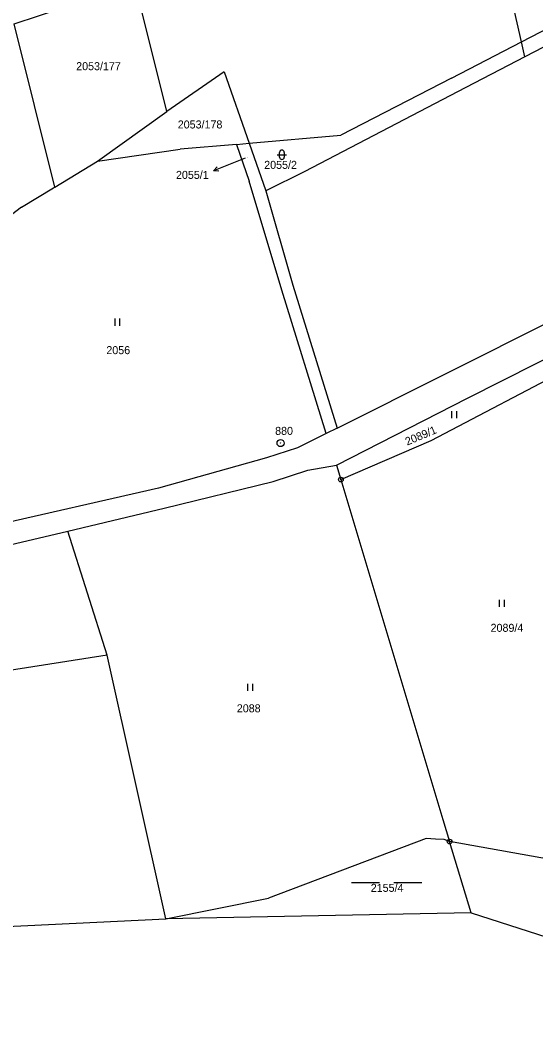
# Model space of a CAD drawing. Extents: x -736345 to -729997, y -1130177 to -1122501.
# Drawn here: x -732550.6 to -732441, y -1128475.7 to -1128261.6 of the extents above; entities that cross this region are included whole.
import ezdxf

# ---------------------------------------------------------------- set-up
doc = ezdxf.new("R2010")
doc.units = 0
for name, color, linetype in [('Vrstva 1', 7, 'Continuous'), ('Vrstva 16', 7, 'Continuous'), ('Vrstva 17', 7, 'Continuous'), ('Vrstva 18', 7, 'Continuous'), ('Vrstva 25', 7, 'Continuous')]:
    doc.layers.add(name, color=color, linetype=linetype)

msp = doc.modelspace()

# ---------------------------------------------------------------- linework, layer by layer
at = {"layer": 'Vrstva 1'}
for points in [[(-732444.11, -1128266.16), (-732456.89, -1128209.92)], [(-732444.11, -1128266.16), (-732412.86, -1128249.98)], [(-732519.44, -1128280.95), (-732526.56, -1128252.5)], [(-732412.09, -1128253.1), (-732443.39, -1128269.35)], [(-732551.87, -1128262.39), (-732541.52, -1128258.95)], [(-732543.26, -1128297.02), (-732551.87, -1128262.39)], [(-732459, -1128273.87), (-732444.11, -1128266.16)], [(-732443.39, -1128269.35), (-732444.11, -1128266.16)], [(-732443.39, -1128269.35), (-732457.71, -1128276.78)], [(-732507.28, -1128272.56), (-732519.44, -1128280.95)], [(-732507.28, -1128272.56), (-732501.97, -1128287.72)], [(-732459, -1128273.87), (-732482.51, -1128285.99)], [(-732457.71, -1128276.78), (-732490.15, -1128293.7)], [(-732483.26, -1128348.19), (-732344.42, -1128278.67)], [(-732534.19, -1128291.5), (-732519.44, -1128280.95)], [(-732501.97, -1128287.72), (-732482.51, -1128285.99)], [(-732534.19, -1128291.5), (-732516.62, -1128288.99)], [(-732504.68, -1128287.96), (-732516.62, -1128288.99)], [(-732504.68, -1128287.96), (-732501.97, -1128287.72)], [(-732504.68, -1128287.96), (-732501.96, -1128295.78)], [(-732501.97, -1128287.72), (-732498.43, -1128297.81)], [(-732543.26, -1128297.02), (-732534.19, -1128291.5)], [(-732490.15, -1128293.7), (-732498.43, -1128297.81)], [(-732494.99, -1128318.93), (-732501.96, -1128295.78)], [(-732550.32, -1128301.31), (-732543.55, -1128297.2)], [(-732543.55, -1128297.2), (-732543.26, -1128297.02)], [(-732498.43, -1128297.81), (-732492.65, -1128317.86)], [(-732550.32, -1128301.31), (-732558.05, -1128307.2)], [(-732485.62, -1128349.38), (-732494.99, -1128318.93)], [(-732492.65, -1128317.86), (-732483.26, -1128348.19)], [(-732455.55, -1128341.87), (-732433.54, -1128330.73)], [(-732463.28, -1128350.81), (-732432.78, -1128334.86)], [(-732483.4, -1128356.05), (-732455.55, -1128341.87)], [(-732485.62, -1128349.38), (-732491.7, -1128352.42)], [(-732483.26, -1128348.19), (-732485.62, -1128349.38)], [(-732482.47, -1128359.13), (-732463.28, -1128350.81)], [(-732491.7, -1128352.42), (-732498.29, -1128354.48)], [(-732498.29, -1128354.48), (-732521.24, -1128360.95)], [(-732489.52, -1128357.12), (-732483.4, -1128356.05)], [(-732483.4, -1128356.05), (-732482.47, -1128359.13)], [(-732496.89, -1128359.52), (-732489.52, -1128357.12)], [(-732520.01, -1128365.17), (-732496.89, -1128359.52)], [(-732482.47, -1128359.13), (-732460.78, -1128431.31)], [(-732521.24, -1128360.95), (-732593.38, -1128377.36)], [(-732540.49, -1128370.07), (-732520.01, -1128365.17)], [(-732610.59, -1128386.6), (-732540.49, -1128370.07)], [(-732532.13, -1128396.4), (-732540.49, -1128370.07)], [(-732532.13, -1128396.4), (-732603.02, -1128407.54)], [(-732519.67, -1128452.42), (-732532.13, -1128396.4)], [(-732460.78, -1128431.31), (-732459.37, -1128435.99)], [(-732464.34, -1128435.36), (-732497.88, -1128447.97)], [(-732462.33, -1128435.46), (-732464.34, -1128435.36)], [(-732460.52, -1128435.57), (-732462.33, -1128435.46)], [(-732459.37, -1128435.99), (-732460.52, -1128435.57)], [(-732454.82, -1128451.13), (-732459.37, -1128435.99)], [(-732435.21, -1128440.32), (-732459.37, -1128435.99)], [(-732519.67, -1128452.42), (-732497.88, -1128447.97)], [(-732594.54, -1128455.99), (-732519.67, -1128452.42)], [(-732454.82, -1128451.13), (-732519.67, -1128452.42)], [(-732454.82, -1128451.13), (-732378.19, -1128475.74)]]:
    msp.add_lwpolyline(points, dxfattribs=at)
at = {"layer": 'Vrstva 16'}
msp.add_lwpolyline([(-732502.8, -1128290.91), (-732506.72, -1128292.48)], dxfattribs=at)
at = {"layer": 'Vrstva 25'}
for points in [[(-732495.49, -1128290.66), (-732495.49, -1128289.66)], [(-732494.49, -1128289.66), (-732494.49, -1128290.66)], [(-732495.99, -1128290.16), (-732493.99, -1128290.16)], [(-732506.72, -1128292.48), (-732509.507, -1128293.589)], [(-732508.393, -1128293.684), (-732509.507, -1128293.589), (-732508.763, -1128292.754)], [(-732530.447, -1128326.465), (-732530.447, -1128324.965)], [(-732529.413, -1128326.465), (-732529.413, -1128324.965)], [(-732458.877, -1128346.115), (-732458.877, -1128344.615)], [(-732457.843, -1128346.115), (-732457.843, -1128344.615)], [(-732448.757, -1128386.175), (-732448.757, -1128384.675)], [(-732447.723, -1128386.175), (-732447.723, -1128384.675)], [(-732502.227, -1128404.015), (-732502.227, -1128402.515)], [(-732501.193, -1128404.015), (-732501.193, -1128402.515)], [(-732480.24, -1128444.66), (-732474.24, -1128444.66)], [(-732471.24, -1128444.66), (-732465.24, -1128444.66)]]:
    msp.add_lwpolyline(points, dxfattribs=at)
for centre, radius in [((-732495.29, -1128351.38), 0.75), ((-732495.29, -1128351.38), 0.032), ((-732482.47, -1128359.13), 0.5), ((-732482.47, -1128359.13), 0.032), ((-732459.37, -1128435.99), 0.5), ((-732459.37, -1128435.99), 0.032)]:
    msp.add_circle(centre, radius, dxfattribs=at)
for centre, start, end in [((-732494.99, -1128289.66), 0.10099, 180.00143), ((-732494.99, -1128290.66), 180.10243, 0.00286)]:
    msp.add_arc(centre, 0.5, start, end, dxfattribs=at)

# ---------------------------------------------------------------- texts
at = {"layer": 'Vrstva 16'}
msp.add_text('2055/1', height=1.7, dxfattribs=at).set_placement((-732517.507, -1128295.29))
at = {"layer": 'Vrstva 17'}
msp.add_text('880', height=1.7, dxfattribs=at).set_placement((-732496.44, -1128349.64))
at = {"layer": 'Vrstva 18'}
for s, height, p in [('2053/177', 1.7, (-732538.71, -1128272.21)), ('2053/178', 1.7, (-732517.13, -1128284.58)), ('2055/1', 0.1, (-732502.6, -1128290.71)), ('2055/2', 1.7, (-732498.76, -1128293.16)), ('2056', 1.7, (-732532.3, -1128332.5)), ('2089/4', 1.7, (-732450.66, -1128391.45)), ('2088', 1.7, (-732504.58, -1128408.54)), ('2155/4', 1.7, (-732476.12, -1128446.66))]:
    msp.add_text(s, height=height, dxfattribs=at).set_placement(p)
msp.add_text('2089/1', height=1.7, rotation=23.00018, dxfattribs=at).set_placement((-732468.375, -1128351.928))

doc.saveas('drawing.dxf')
